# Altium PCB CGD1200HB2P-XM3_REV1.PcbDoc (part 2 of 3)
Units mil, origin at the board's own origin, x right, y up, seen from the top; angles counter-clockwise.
Board outline 2086.61 x 3149.61 mil, 6 copper layers (TOP, LAYER2, LAYER3, LAYER4, LAYER5, BOTTOM), stack 57.2 mil thick; 178 components, 101 nets, 513 pads, 419 vias.
Unrouted connection lines stored in the file: 206.
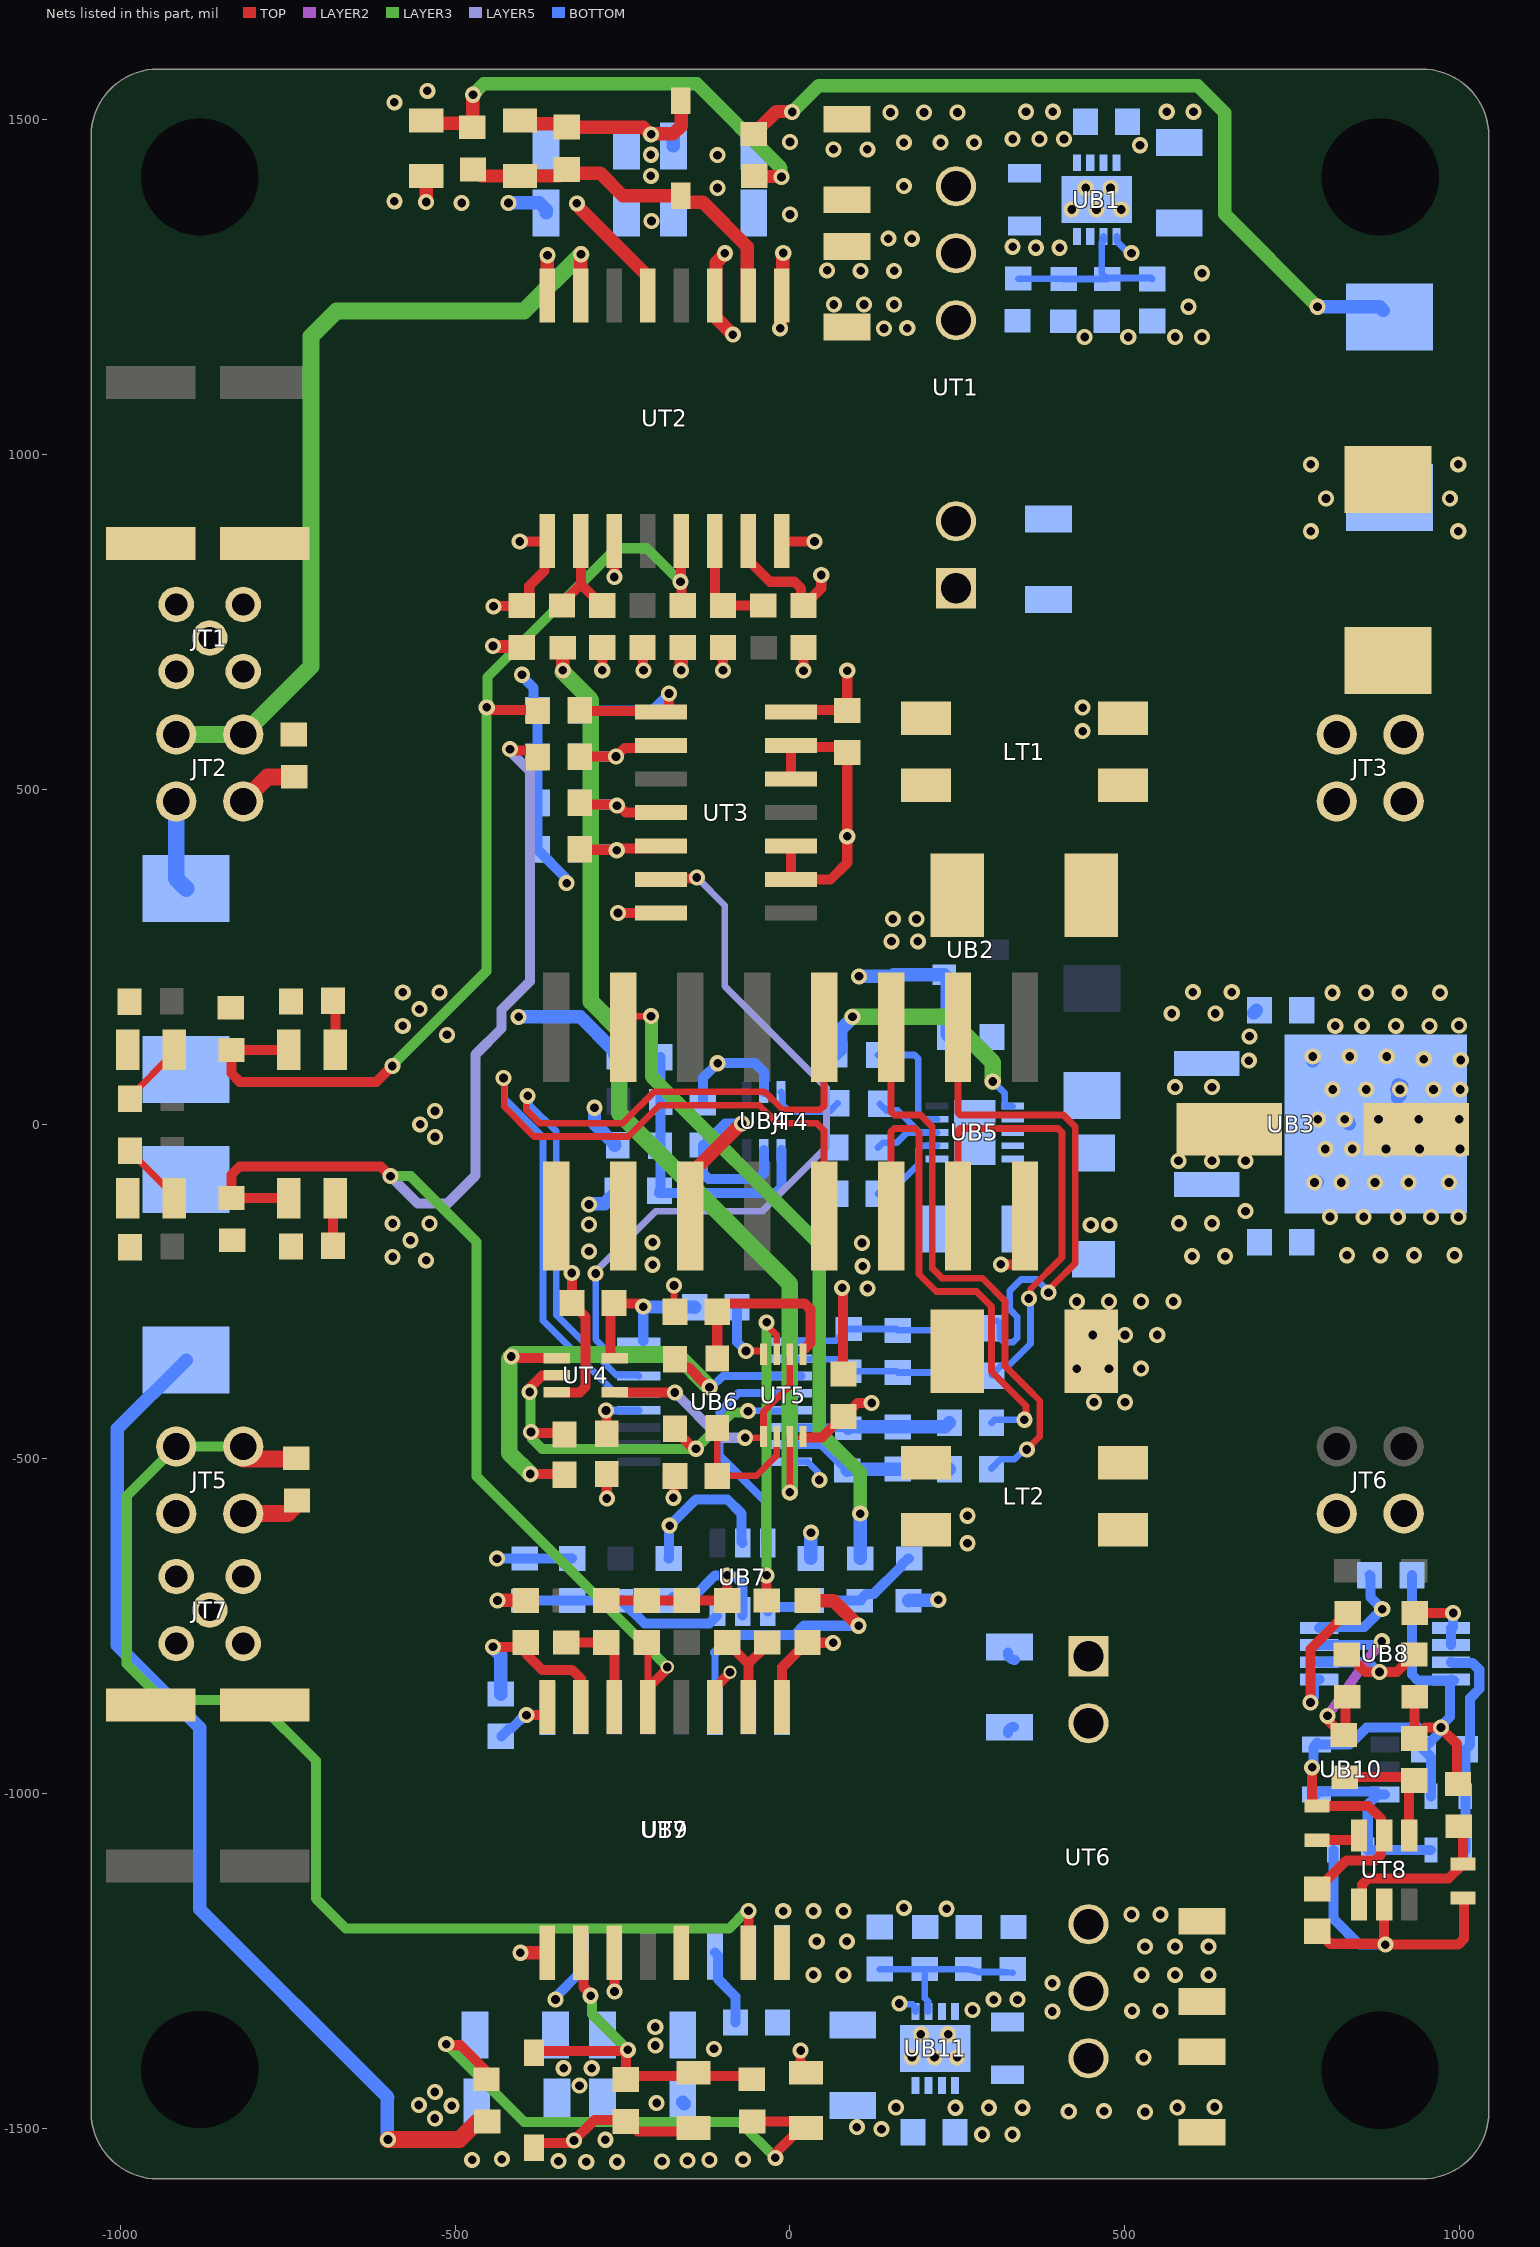
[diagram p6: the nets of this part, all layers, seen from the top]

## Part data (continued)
UB2: library part MOSFET_P_GSD, "MOSFET P-CH 30V 4.3A SOT23", Manufacturer="Diodes Incorporated", Package Size="TO-236-3, SC-59, SOT-23-3"
UB3: "IC REG LINEAR 5V 1A DPAK", Manufacturer="ON Semiconductor", Package Size="TO-252-3, DPak (2 Leads + Tab), SC-63"
UB4: library part BUFFER_2X_6P, "IC BUF NON-INVERT 5.5V SC70-6", Manufacturer="Texas Instruments", Package Size="6-TSSOP, SC-88, SOT-363", Supplier Part Number 1=595-SN74LVC2G17DCKR, Supply Voltage="1.65V ~ 5.5V"
UB5: library part MP5000A_5, "IC CURR LIMIT SWITCH", Manufacturer="Monolithic Power Systems Inc.", Package Size="10-VFDFN Exposed Pad", Supply Voltage="Not Required"
UB6: library part SN65C1167, "IC DIFF DVR/RCVR DUAL 16-TSSOP", Manufacturer="Texas Instruments", Manufacturer PN=SN65C1167EPWR, Package Size="16-TSSOP (0.173\", 4.40mm Width)", Supply Voltage="4.5V ~ 5.5V"
UB7: library part SN74LVC2G04, "IC INVERTER DUAL SHMT-T SOT-23-6", Manufacturer="Texas Instruments", Package Size=SOT-23-6, Supplier Part Number 1=74AH4903, Supply Voltage="1.65 V - 5.5 V"
UB8: "IC OPAMP GP 2 CIRCUIT 8MSOP", Case/Package=MSOP, Input Bias Current=1pA, Input Offset Voltage (Vos)=3mV, Input Offset Voltage-Max=5mV, Manufacturer=Microchip, Max Operating Temperature=125°C, Max Supply Voltage=5.5V, Min Operating Temperature=-40°C, Min Supply Voltage=2.4V, Nominal Supply Current=1mA, Output Current=25mA, Package Quantity=100, Power Supply Rejection Ratio (PSRR)=70dB, Supplier Part Number 1=MCP6292-E/MS-ND, Voltage Gain=110dB
UB9: "DGTL ISO 5.7KV GEN PURP 16SOIC", Manufacturer="Texas Instruments", Package Size="16-SOIC (0.295\", 7.50mm Width)", Supplier Part Number 1=595-ISO7810DWR, Supply Voltage="2.25V ~ 5.5V"
UB10: "IC VREF SHUNT ADJ 2% SOT23-5", Case/Package=SOT-23-5, Cathode Current=60uA, Manufacturer=STMicroelectronics, Max Input Voltage=10V, Max Operating Temperature=125°C, Max Output Current=30mA, Max Output Voltage=6V, Min Operating Temperature=-40°C, Min Output Voltage=1.24V, Package Quantity=1, Supplier Part Number 1=511-TS431IYLT, Temperature Coefficient=100ppm/°C, Tolerance=2%
UT1 UT6: library part MGJ2, "DC/DC CONVERTER 15V -5V 2W", Manufacturer="Murata Power Solutions Inc.", Package Size="0.77\" L x 0.39\" W x 0.50\" H (19.7mm x 10.0mm x 12.7mm)", Rated Power=2W, Supply Voltage="10.8 - 13.2 V"
UT2 UT7: "1500V ISOLATED HI UVLO 14.5V GAT", Manufacturer="Analog Devices", Manufacturer Part Number=ADUM4146CRWZ, Supplier Part Number 1=ADUM4146ARWZ
UT3: library part AND4_2X, "IC GATE AND 2CH 4-INP 14SOIC", Manufacturer="Texas Instruments", Manufacturer PN=SN74HC21DR, Package Size="14-SOIC (0.154\", 3.90mm Width)", Supplier Part Number 1=296-14842-1-ND, Supply Voltage="2 V - 6 V"
UT4: library part SN74LVC1G32, "IC GATE OR 1CH 2-INP SC-70-5", Manufacturer="Texas Instruments", Package Size="5-TSSOP, SC-70-5, SOT-353", Supply Voltage="1.65 V - 5.5 V"
UT5: library part XOR2_2X, "IC GATE XOR 2CH 2-INP US8", Manufacturer="ON Semiconductor", Manufacturer PN=NL27WZ86USG, Package Size="8-VFSOP (0.091\", 2.30mm Width)", Supply Voltage="1.65 V ~ 5.5 V"
UT8: library part LTC6992CS6-2, "IC OSC SILICON PROG TSOT23-6", Case/Package=SOT-23-6, Frequency=3.81Hz, Manufacturer="Analog Devices / Linear Technology", Max Operating Temperature=70°C, Max Supply Voltage=5.5V, Min Operating Temperature=0°C, Min Supply Voltage=2.25V, Operating Supply Current=365uA, Package Quantity=500, Supplier Part Number 1=584-C6992CS6-2TRMPBF

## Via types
v1: diameter 24.02, hole 12.99, TOP to BOTTOM, tented both sides, 415 vias
v2: diameter 20, hole 12.99, TOP to BOTTOM, tented both sides, 4 vias

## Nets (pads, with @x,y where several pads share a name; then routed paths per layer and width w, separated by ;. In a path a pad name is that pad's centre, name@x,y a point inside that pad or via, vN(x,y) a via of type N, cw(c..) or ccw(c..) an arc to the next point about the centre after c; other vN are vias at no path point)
0: CB9.2 CB10.2 CB11.2 CB12.2 CB13.1 CB14.1 CB15.2 CB16.2 CB17.2 CB18.2 CB19.2 CB20.1 CB21.2 CB24.2 CB25.2 CB26.2 CB29.1 CT4.2 CT5.2 CT6.2 CT7.2 CT8.2 CT9.2 CT10.2 CT11.2 CT12.2 CT13.2 CT14.2 CT15.2 CT16.2 CT17.2 CT18.2 CT19.2 CT20.2 CT21.2 DB4.C DT3.2 DT5.2 JT4.2 JT4.12 JT4.14 JT4.16 LT1.2 LT2.2 RB6.2 RB15.1 UB2.1 UB3.2 UB4.2 UB5.1 UB6.8 UB7.2 UB9.9 UB9.16 UT2.1 UT2.3 UT2.8 UT3.7 UT3.9 UT3.10 UT3.12 UT3.13 UT4.3 UT5.4 UT7.1 UT7.3 UT7.8 | length 4081.8
  TOP w10: v1(-173.14,-240.98) -173.14,-278.42 CT13.2@-172.1,-279.46 ; v1(-65.61,-338.99) -39.53,-338.99 UT5.4@-39.53,-343.73
  TOP w15: v1(-442.4,772.71) -441.73,773.37 -400.91,773.37 CT4.2@-400.24,774.04 -399.26,774.04 -389.19,784.11 -389.19,803.19 -366.12,826.26 -366.12,866.17 UT2.1@-362.01,870.28 ; v1(-403.31,869.48) UT2.1@-369.09,869.48 ; v1(-393.31,-882.45) -366.12,-882.45 -366.12,-874.71 UT7.8@-362.01,-870.59 ; UT4.3@-348.31,-400.65 -313.79,-400.65 -305.01,-391.86 -305.01,-288.22 -313.79,-279.44 -314.3,-279.44 -325.5,-268.24 CT12.2@-325.5,-267.25 -325.62,-267.13 -325.62,-222.64 v1(-325.74,-222.52) ; v1(-280.13,677.17) CT5.2@-280.13,711.05 ; CT16.2@-274.04,-711.16 CT17.2@-92.89,-711.16 ; v1(-262.09,816.54) v1(-262.09,816.54) UT2.3@-262.01,870.28 UT2.3@-262.01,870.28 ; v1(-256.78,314.94) UT3.7@-207.08,314.94 ; CT6.2@-220.08,711.05 -219.37,710.34 -219.37,677.88 v1(-218.66,677.17) v1@-218.66,675.94 ; v1(-174.12,-557.99) -172.81,-556.68 -172.81,-526.74 CT15.2@-171.5,-525.43 ; CT7.2@-162.38,692.35 -161.62,693.12 CT7.2@-161.62,709.46 ; UT7.3@-112.01,-870.59 -112.01,-841.85 -89.5,-819.34 v2(-89.5,-818.23) ; v1(-99.93,677.17) CT8.2@-99.95,711.03 ; CT17.2@-93.88,-711.16 CT17.2@-92.89,-711.16 ; v1(-93.74,-673.78) -93.81,-673.85 -93.81,-710.25 CT17.2@-92.89,-711.16 ; UT7.1@-12.01,-870.59 -12.19,-870.41 -12.19,-811.59 14.05,-785.36 15.03,-785.36 CT21.2@26.23,-774.16 26.44,-774.37 64.27,-774.37 v1(64.48,-774.58) ; UT2.8@-12.01,870.28 -11.21,869.48 v1(36.69,869.48) ; UT3.10@1.55,414.94 UT3.9@1.55,364.94 60.4,364.94 85.52,390.06 CT10.2@85.52,554.42 77.33,562.61 1.55,562.61 UT3.12@1.55,514.94 ; v1(20.15,676.67) CT9.2@20.14,711.05 ; v1@77.94,-249.52 78.97,-250.54 78.97,-372.46 CT14.2@79.99,-373.48 ; v1(314.85,-209.45) 338.76,-209.45 350.94,-197.27 JT4.2@350.94,-109.81
  TOP w20: v1(-436.42,-711.16) CT20.2@-394.15,-711.16 ; UT2.1@-362.01,870.28 UT2.1@-360.39,871.9 ; v1@-162.38,676.52 CT7.2@-162.38,692.35 ; CT7.2@-161.62,709.46 CT7.2@-160.02,711.05 ; JT4.12@-149.06,-137.37 -149.06,-75.36 -73.61,0.08 -72.44,0.08 v1(-71.67,0.85) ; v1@-99.93,675.05 v1(-99.93,677.17) ; CT11.2@935.04,3.19 v1(938.74,6.89)
  BOTTOM w10: UB6.8@0.42,-504.19 26.42,-504.19 41.26,-519.02 41.26,-528.84 v1(43.94,-531.52)
  BOTTOM w15: v1(-437.29,-648.78) -437.18,-648.67 -396.22,-648.67 RB15.1@-396.11,-648.56 CB24.2@-325.04,-648.56 ; CB29.1@-430.6,-913.95 -418.42,-901.77 -415.06,-901.77 -395.75,-882.45 -366.32,-882.45 -362.01,-878.14 UB9.9@-362.01,-871.18 ; v1(-400,670.68) -400,668.24 -382.58,650.81 -382.58,623.43 CB9.2@-376.56,617.41 ; CB9.2@-376.56,618.4 CB10.2@-376.56,548.36 -376.56,409.26 -335.04,367.74 -335.04,361.21 v1(-333.31,359.48) ; CB26.2@-180.93,-711.55 -175.35,-705.97 -143.97,-705.97 -112.16,-674.17 -94.13,-674.17 v1(-93.74,-673.78) -92.02,-675.51 -81.51,-675.51 -70.54,-686.47 UB7.2@-70.54,-733.44 ; CB21.2@-79.13,-273.8 -79.13,-325.47 v1(-65.61,-338.99) ; v1(-71.67,0.85) -96.61,0.87 -129.02,-31.54 CB15.2@-130,-31.54 -130,-73.46 -121.22,-82.25 -47.84,-82.25 -39.06,-73.46 UB4.2@-39.06,-38.82 ; UB9.16@-12.01,-871.18 -12.01,-811.41 24.83,-774.58 v1(64.48,-774.58)
  BOTTOM w20: v1(-405,159.95) -313.25,159.95 -263.76,110.47 -261.5,108.21 RB6.2@-261.5,103.98 ; v1(-300,-120.05) -299.24,-119.28 -276.76,-119.28 -257.87,-100.39 CB17.2@-257.87,-99.41 ; CB25.2@30.94,-648.56 31.23,-648.27 31.23,-610.25 v1(31.53,-609.96) ; v1(102.94,220.48) 152.49,220.48 154.95,222.94 UB2.1@230.49,222.94 234.5,218.94 234.5,133.94 CB14.1@238.5,129.94 ; UB3.2@780.4,94.04 v1(780.4,100.82) ; v1(782.95,-87.21) UB3.2@787.34,-87.21 ; v1(828.24,6.89) UB3.2@835.19,-0.06 ; v1(873.36,-87.21) UB3.2@874.49,-86.08 ; UB3.2@874.49,-0.06 UB3.2@896.71,-0.06 ; UB3.2@878.47,1.67 v1(878.47,6.89) ; UB3.2@905.43,51.48 910.54,56.59 UB3.2@913.13,56.59 ; UB3.2@907.13,38.9 UB3.2@907.13,54.89 ; UB3.2@908.19,51.48 UB3.2@908.19,58.94 ; UB3.2@910.54,42.3 v1(910.54,51.48) ; v1(938.74,6.89) UB3.2@955.83,6.89
  other v1: 265.11,-625.88 265.11,-584.74 115.99,-245.3 77.94,-244.52 108.5,-212.31 -205,-210.05 831.4,-195.87 881.62,-195.87 931.85,-195.87 992.13,-195.87 -300,-190.05 107.65,-177.62 -204.99,-176.64 -300,-150.05 449.01,-150.52 476.69,-150.52 806.24,-138.78 856.47,-138.78 907.48,-138.78 956.93,-138.78 998.03,-138.78 823.13,-87.21 923.59,-87.21 983.86,-87.21 799.21,-37.4 839.4,-37.4 889.62,-37.4 939.85,-37.4 1000.12,-37.4 -529.74,-19.52 -552.06,-0.52 788.06,6.89 999.02,6.89 -529.74,19.48 810.08,51.48 860.31,51.48 960.55,51.48 1000.6,51.48 1001.4,95.45 946.15,96.81 835.65,100.82 890.9,100.82 814.02,146.56 854.2,146.56 904.43,146.56 954.66,146.56 998.88,147.04 809.74,195.87 859.97,195.87 910.2,195.87 970.47,195.87 85.52,429.43 436.94,586.48 436.94,621.48 -162.38,677.17
5V: CB13.2 CB15.1 CB21.1 CB26.1 CB29.2 CT4.1 CT9.1 CT10.1 CT12.1 CT14.1 CT20.1 CT21.1 RB9.1 RB14.2 RT14.1 RT15.2 RT16.1 RT19.1 RT20.1 RT21.2 RT24.2 RT26.2 UB3.3 UB4.5 UB6.12 UB6.16 UB7.5 UB9.14 UT2.7 UT3.14 UT4.5 UT5.8 UT7.7 | length 2116.1
  TOP w15: v1(-443.31,-780.52) -400.51,-780.52 CT20.1@-394.15,-774.16 -394.15,-790.71 -370.01,-814.86 -325.2,-814.86 -312.01,-828.06 UT7.7@-312.01,-870.59 ; v1(-274.56,-427.67) -274.03,-428.19 -274.03,-462.03 RT24.2@-273.51,-462.56 ; RT26.2@-273.51,-522.56 -273.51,-558.8 v1(-273.27,-559.04) ; UT4.5@-261.7,-349.47 -267.47,-349.47 -267.84,-349.09 -267.84,-272.59 CT12.1@-262.51,-267.25 -261.91,-267.85 -226.16,-267.85 -221.41,-272.59 v1(-218.97,-272.59) ; UT2.7@-62.01,870.28 -62.01,841.54 -29.95,809.48 6.69,809.48 16.69,799.48 16.69,777.49 CT9.1@20.14,774.04 21.13,774.04 46.69,799.6 v1(46.69,819.48) ; UT3.14@1.55,614.94 4.54,617.93 CT10.1@85,617.93 ; UT5.8@19.52,-467.98 47.51,-467.98 79.01,-436.47 80.98,-436.47 100.94,-416.52 v1(121.94,-416.52) ; CT10.1@85.52,617.42 CT10.1@85,617.93 ; v1(85.52,676.67) 85.52,618.45 CT10.1@85,617.93
  TOP w20: v1(-443.27,713.55) -442.5,712.78 -401.97,712.78 CT4.1@-400.24,711.05 ; CT21.1@26.23,-711.16 26.62,-711.55 65.05,-711.55 v1(102.49,-748.99) ; v1(635,164.95) v1@635.76,164.19
  BOTTOM w10: UB9.14@-112.01,-871.18 -112.01,-789.21
  BOTTOM w12: v1@-274.75,-427.86 -274.42,-427.53 -226.35,-427.53 UB6.12@-226.21,-427.67
  BOTTOM w15: UB6.16@-218.97,-323.99 v1(-218.97,-272.59) ; CB26.1@-180.93,-648.56 -180.27,-647.9 -180.27,-600.21 -140.58,-560.52 -93.31,-560.52 -72.62,-581.21 -72.62,-623.29 UB7.5@-70.54,-625.36 ; CB15.1@-130,31.45 -130,68.53 -107.33,91.21 -52.56,91.21 -39.06,77.71 UB4.5@-39.06,47.96 ; -112.01,-789.21 -85.67,-762.88 6.83,-762.88 20.71,-748.99 v1(102.49,-748.99)
  BOTTOM w20: v1(-443.31,-780.52) -443.31,-781.6 -431.59,-793.33 CB29.2@-431.59,-850.96 ; v1(-291.8,24.3) -291.8,0.23 -261.5,-30.08 RB9.1@-261.5,-32.05 ; v1(-218.97,-272.59) -218.37,-273.2 -142.73,-273.2 CB21.1@-142.12,-273.8 ; RB14.2@177.02,-711.55 177.72,-710.85 220.64,-710.85 v1(221.34,-710.15) ; v1(635,164.95) v1@635.76,165.72 ; CB13.2@692.37,165.72 CB13.2@696.47,169.82
  other v1: -179.61,-599.55 -543.06,-203.52 -593.06,-198.52 -566.32,-173.52 -593.06,-148.52 -538.06,-148.52 575,54.95 630,54.95 -107.92,90.62 685.04,94.49 686.02,130.91 -512.06,133.09 -578.06,146.48 570,164.95 -553.06,171.48 -578.06,196.48 -523.06,196.48 601.38,196.85 659.45,196.85
12V: CB14.2 CB20.2 CT11.1 UB2.2 UB3.1 UB5.11
  other v1: 600.39,-197.37 649.6,-197.37 580.7,-148.15 629.92,-148.15 680,-130.05 580,-55.05 630,-55.05 680,-55.05 151.57,272.64 190.94,272.64 153.54,306.1 188.98,306.1
12V_SWITCHED: CB19.1 FT1.1 FT2.1 RB5.1 UB5.6 UB5.7 UB5.8 UB5.9 UB5.10 | length 485.1
  TOP w20: v1(428.19,-365.24) 428.19,-361.16 FT2.1@449.99,-339.36 ; v1(452.22,-315.12) 449.99,-317.34 FT2.1@449.99,-339.36 ; v1(476.24,-365.24) 450.37,-339.36 FT2.1@449.99,-339.36
  LAYER3 w25: v1(93.46,159.92) 235.02,159.92 302.7,92.24 v1(302.7,63.54)
  BOTTOM w10: v1(302.7,63.54) 320.78,45.46 320.78,26.8 320.9,26.68 UB5.6@332.41,26.68
  BOTTOM w20: RB5.1@68.5,104.04 76.21,111.75 76.21,141.59 93.46,158.83 v1(93.46,159.92)
  other v1: 453.74,-415.35 500.27,-415.35 524.3,-365.24 500.27,-315.12 548.32,-315.12 428.19,-265 476.24,-265 524.3,-265 572.35,-265
-5V_HS: CB1.2 CT3.2 RB1.1 UB1.1 UB1.2 UB1.3 UB1.9 UT1.5 | length 1.1
  TOP w20: v1(140.43,1187.58) v1@141.52,1187.58
  other v1: 175.08,1188 65.51,1223.43 110.51,1223.43 155.51,1223.43 420.53,1365.13 457.56,1365.13 494.58,1365.13 441.51,1397.12 478.53,1397.12 332.49,1470.23 372.49,1470.23 408.94,1470.23 352.49,1511.01 392.49,1511.01
-5V_LS: CB38.2 CT24.2 RB22.1 UB11.1 UB11.2 UB11.3 UB11.9 UT6.5
  other v1: 286.94,-1508.52 331.94,-1508.52 246.94,-1468.52 296.94,-1468.52 346.94,-1468.52 182.09,-1393.23 215.82,-1393.23 249.56,-1393.23 195.43,-1358.78 236.22,-1358.78 530,-1228 575,-1228 625,-1228 510,-1180.05 552.87,-1180.05
FAULT: UB6.15 UT3.6 | length 1136.9
  TOP w15: UT3.6@-191.99,365.41 -190.88,366.51 -140.57,366.51 v1(-139,368.08)
  TOP w20: UT3.6@-192.45,364.94 UT3.6@-191.99,365.41
  LAYER5 w10: v1(-290,-223.05) -290,-220.05 -200,-130.05 -41.09,-130.05 54.68,-34.28 54.68,54 -97.51,206.19 -97.51,326.59 v1(-139,368.08)
  BOTTOM w10: v1(-290,-223.05) -290,-321.43 -262.35,-349.09 -227.08,-349.09 UB6.15@-225.58,-350.59
FAULT-Output_N: JT4.8 UB6.13 | length 1248.3
  TOP w10: v1(-427.48,68.53) -426.35,67.4 -426.35,25.72 -381.92,-18.71 -241.33,-18.71 -194.66,27.96 -45.81,27.96 -19.11,1.26 39.73,1.26 50.78,-9.79 50.78,-109.65 JT4.8@50.94,-109.81
  BOTTOM w10: v1(-427.48,68.53) -426.35,67.4 -426.35,38.05 -368.74,-19.56 -368.74,-293.6 -267.66,-394.69 -262.06,-400.29 -227.08,-400.29 UB6.13@-225.58,-401.79
FAULT-Output_P: JT4.7 UB6.14 | length 1130.1
  TOP w10: v1(-391.49,41.96) -393.8,39.65 -393.8,21.46 -373.64,1.29 -249.61,1.29 -202.95,47.96 -37.53,47.96 -10.83,21.26 44.92,21.26 50.78,27.12 50.78,143.97 JT4.7@50.94,144.13
  BOTTOM w10: v1(-391.49,41.96) -388.81,39.28 -388.81,28.79 -348.74,-11.27 -348.74,-285.32 -259.38,-374.69 -227.08,-374.69 UB6.14@-225.58,-376.19
FLT_HS: CT7.1 DT4.2 RT9.1 RT16.2 UT2.5 | length 1578.7
  TOP w15: DT4.2@-748.5,110.78 -748.76,110.52 RT16.2@-833.64,110.52 -833.64,75.31 -821.33,63 -617.25,63 v1(-593.56,86.7) ; v1(-452.68,621.9) -450.24,621.9 -446.3,617.96 -378.08,617.96 RT9.1@-376.56,616.43 ; v1(-163.31,809.48) -161.67,807.84 -161.67,775.69 CT7.1@-160.02,774.04 ; v1@-162.01,810.79 -162.66,811.44 -162.66,869.63 UT2.5@-162.01,870.28
  LAYER3 w15: v1(-593.56,86.7) -593.56,87.67 -453.31,227.91 -453.31,621.26 -451.52,623.06 -451.52,667.39 -259.42,859.48 -213.31,859.48 v1(-163.31,809.48)
FLT_LS: CT18.1 DT6.2 RT11.1 RT19.2 UT7.5 | length 2408.7
  TOP w10: UT7.5@-212.01,-899.33 CT18.1@-212.01,-774.16
  TOP w15: DT6.2@-748.5,-110.9 -748.76,-110.64 RT19.2@-833.64,-110.64 -833.64,-75.42 -821.62,-63.4 -610.73,-63.4 v1(-596.25,-77.88) ; v1@-420.8,559.48 v1@-419.08,557.76 ; v1(-417.81,559.48) -416.08,557.76 -386.77,557.76 -376.56,547.54 RT11.1@-376.56,547.38 ; UT7.5@-212.01,-899.33 -212.01,-841.85 -185.04,-814.88 -185.04,-812.24 v2(-183.31,-810.52)
  LAYER3 w15: v1(-596.25,-77.88) -565.96,-77.88 -537.61,-106.23 -468.01,-175.84 -468.01,-525.82 v2(-183.31,-810.52)
  LAYER5 w15: v1(-596.25,-77.88) -555.15,-118.97 -511.4,-118.97 -469.62,-77.19 -469.62,103.48 -430.51,142.58 -430.51,170.52 -388.01,213.02 -388.01,526.69 -417.81,556.49 v1(-417.81,559.48)
"Gate Sense HS": JT1.1 JT2.1 JT2.3 RT5.2 RT6.2 RT10.1 UT2.15 | length 1251.3
  TOP w20: UT2.15@-312.01,1236.82 v1(-312.01,1298.32)
  LAYER3 w25: JT2.1@-916.15,581.45 JT2.3@-816.15,581.45 -715.01,682.59 -715.01,1175.53 -677.06,1213.48 -396.84,1213.48 v1(-312.01,1298.32)
"Gate Sense LS": JT5.1 JT5.3 JT7.1 RT25.1 RT33.2 RT34.2 UT7.15 | length 1853.2
  TOP w15: UT7.15@-61.91,-1237.03 -61.96,-1236.98 -61.96,-1174.59 v1(-61.91,-1174.54)
  TOP w20: UT7.15@-62.01,-1237.13 UT7.15@-61.91,-1237.03
  TOP w25: JT5.3@-827.51,-488.99 -816.44,-500.06 RT25.1@-732.13,-500.06
  LAYER2 w10: JT5.3@-832.08,-493.54 JT5.3@-832.08,-481.54
  LAYER3 w15: JT5.3@-816.15,-481.54 JT5.1@-916.15,-481.54 -990,-555.4 -990,-806.02 -935.98,-860.05 -797.75,-860.05 -707.48,-950.31 -707.48,-1156.35 -662.69,-1201.14 -90.95,-1201.14 -64.35,-1174.54 v1(-61.91,-1174.54)
HS-DRAIN: DT2.C JT3.1 JT3.2 JT3.3 JT3.4
HS-PWM: RT8.1 UT5.7 | length 1485.1
  TOP w10: v1(-0.16,-549.9) UT5.7@-0.16,-466.23
  TOP w20: RT8.1@-339.21,711.05 -339.14,710.99 -339.14,677.23 v1(-339.08,677.17) v1@-339.08,674.43
  LAYER3 w25: v1@-339.08,674.43 -297.31,632.66 -297.31,182.63 -255.01,140.33 -255.01,16.1 -0.16,-238.74 v1(-0.16,-549.9)
HS-PWM-INPUT: RT22.1 RT26.1 UB6.3 UT4.1 | length 838.2
  TOP w15: v1(-415.94,-347.2) -413.5,-347.2 -411.23,-349.47 UT4.1@-348.31,-349.47 ; v1(-387.51,-522.56) -336.5,-522.56 RT26.1@-336.5,-523.54 ; RT22.1@-171.5,-351.04 -171.5,-353.01 -161.29,-363.23 -151.13,-363.23 -139.73,-374.63 -139.73,-375.33 -122.04,-393.02 v1(-120.05,-393.02)
  LAYER3 w25: v1(-415.94,-347.2) -419.06,-350.32 -419.06,-491.01 v1(-387.51,-522.56) ; v1@-412.82,-344.09 -168.99,-344.09 v1(-120.05,-393.02)
  BOTTOM w12: v1(-120.05,-393.02) -116.81,-393.02 -99.98,-376.19 UB6.3@17.47,-376.19
HS-PWM_N: JT4.4 LB2.1 | length 672.7
  TOP w10: JT4.4@250.94,-109.81 250.94,-11.31 cw(c255.63,-11.31) 255.63,-6.62 400.15,-6.62 406,-12.48 406,-199.24 359.37,-245.87 359.37,-257.84 v1(356.69,-260.52)
  BOTTOM w10: LB2.1@301.49,-374.56 315.19,-360.86 326.37,-360.86 359.2,-328.04 359.2,-266.99 356.69,-264.48 v1(356.69,-260.52)
HS-PWM_P: JT4.3 LB1.1 | length 755.3
  TOP w10: JT4.3@250.94,116.57 250.94,18.07 ccw(c255.63,18.07) 255.63,13.38 408.43,13.38 426,-4.19 426,-207.52 393.08,-240.44 393.08,-240.9 386.08,-247.91 v1(386.08,-251.71)
  BOTTOM w10: LB1.1@309.64,-293.93 313.34,-297.63 313.34,-319.75 319.2,-325.61 333.34,-325.61 339.2,-319.75 339.2,-287.81 328.22,-276.82 328.22,-248.72 344.89,-232.04 368.48,-232.04 386.08,-249.64 v1(386.08,-251.71)
HS-SOURCE: CB1.1 CB2.1 CB3.2 CB4.2 CB5.1 CB6.2 CT1.2 CT2.2 CT3.1 DB2.C DT1.A JT1.2 JT1.3 JT1.4 JT1.5 JT2.2 JT2.4 RB2.2 RT2.2 RT10.2 UB1.4 UB1.5 UT1.6 UT2.11 | length 708.7
  TOP w20: RT2.2@-403.06,1497.82 -398.13,1492.9 -337.98,1492.9 CT2.2@-332.92,1487.84 ; CT2.2@-333.06,1487.98 CT2.2@-332.92,1487.84 ; DT1.A@-163.06,1527.35 -162.43,1526.72 -162.43,1489.85 -174.14,1478.13 -206.47,1478.13 v1(-207.24,1477.36) -208.32,1477.36 -218.8,1487.84 CT2.2@-332.92,1487.84 ; v1(-97.23,1299.79) -97.23,1298.71 -110.39,1285.54 -110.39,1203.38 v1(-85.29,1178.28)
  TOP w25: JT2.4@-816.15,481.45 -779.79,517.81 -740.65,517.81 RT10.2@-740,518.46
  BOTTOM w10: UB1.5@487.61,1324.82 487.61,1318.32 503.3,1302.64 507.31,1302.64 v1(510,1299.95)
  BOTTOM w20: CB2.1@-174.01,1459.94 CB2.1@-174.01,1474.94
  BOTTOM w25: JT2.2@-916.15,481.45 -916.15,366.32 DB2.C@-901.31,351.48
  other v1: 105.51,1273.62 155.51,1273.62 55.48,1274.37 146.93,1321.61 181.94,1321.48 -206.7,1347.91 -207.68,1415.35 -207.68,1446.85 522.49,1461.01 562.49,1511.01 602.49,1511.01
HS-VDD: CB3.1 CB6.1 CT1.1 RT1.1 UT1.7 UT2.13 | length 285.2
  TOP w20: v1(-543.06,1376.48) RT1.1@-543.06,1415.14 ; v1(-318.13,1374.27) -317.36,1373.51 -317.36,1370.91 -213.62,1267.17 -213.62,1238.43 UT2.13@-212.01,1236.82
  BOTTOM w20: v1(-420,1374.95) -374.01,1374.95 -364.01,1364.95 CB6.1@-364.01,1359.94
  other v1: -490,1374.95 -590.56,1377.44 170,1399.95 65,1454.95 115.51,1454.95 170,1464.95 225,1464.95 275,1464.95 150,1509.95 200,1509.95 250,1509.95 -590.56,1525.07 -541.34,1542.32
HS-VSS: CB2.2 CB4.1 CB5.2 CB7.1 RB1.2 RB3.1 RB4.1 UB1.7 UB1.8 UT2.9 UT2.16 | length 174.6
  TOP w20: UT2.16@-362.01,1236.82 v1(-362.01,1296.86) ; v1(-14.59,1187.72) -14.59,1188.81 -13.62,1189.78 -13.62,1235.2 -10.73,1238.09 -10.73,1299.55 v1(-9.96,1300.32)
  other v1: 440,1174.95 505,1174.95 575,1174.95 615,1174.95 595,1219.95 615,1269.95 367.13,1308.07 402.56,1308.07 332.49,1309.48 0,1357.75 -108.27,1397.12 -108.27,1446.33 0,1466.02
LOGIC-ENABLE: JT4.13 RB13.2 | length 1013.6
  TOP w10: JT4.13@-249.06,116.57 -249.06,141.5 -229.55,161.01 v1(-207.51,161.01)
  LAYER3 w20: v1(-207.51,161.01) -206.74,160.24 -206.74,70.93 43.94,-179.76 43.94,-459.01 104.99,-520.06 v1(104.99,-581.7)
  BOTTOM w20: RB13.2@104.99,-648.56 v1(104.99,-581.7)
LS-PWM: RT30.1 UT5.3 | length 474.2
  TOP w10: v1(-34.83,-296.06) -34.83,-299.85 -19.85,-314.83 UT5.3@-19.85,-348.98
  TOP w15: RT30.1@-34.81,-711.16 v1@-34.81,-671.73
  LAYER3 w15: v1@-34.82,-671.72 v1@-34.82,-296.07
  other v1: -34.81,-673.78
LS-PWM-INPUT: RT23.1 RT24.1 UB6.5 UT4.2 | length 633.9
  TOP w15: v1(-388.55,-400.05) -386.82,-398.32 -386.82,-392.51 -369.75,-375.43 -348.69,-375.43 UT4.2@-348.31,-375.06 ; v1(-386.64,-459.86) -384.92,-461.58 -339.54,-461.58 RT24.1@-337.82,-459.86 ; RT23.1@-171.5,-456.7 -145.1,-483.1 -141.89,-483.1 v1(-140.17,-484.83)
  LAYER3 w15: v1(-388.55,-400.05) -387.6,-401 -387.6,-458.9 -384.92,-461.58 -384.92,-469.86 -369.95,-484.83 v1(-140.17,-484.83) -85.7,-430.36 -64.25,-430.36 v1(-62.52,-428.63)
  BOTTOM w10: v1(-62.52,-428.63) -61.9,-428.01 -0.2,-428.01 UB6.5@0.42,-427.39
LS-PWM_N: JT4.6 LB3.1 | length 727.1
  TOP w10: JT4.6@150.94,-109.81 150.94,-11.31 155.63,-6.62 186.75,-6.62 192.61,-12.48 192.61,-224.26 218.42,-250.06 278.75,-250.06 300.99,-272.3 300.99,-369.4 346.57,-414.98 352.43,-420.83 352.43,-439.03 v1(349.94,-441.52)
  BOTTOM w10: LB3.1@300.87,-446.08 305.43,-441.52 v1(349.94,-441.52)
LS-PWM_P: JT4.5 LB4.1 | length 825.3
  TOP w10: JT4.5@150.94,116.57 150.94,18.07 155.63,13.38 195.04,13.38 212.61,-4.19 212.61,-215.97 226.7,-230.06 287.04,-230.06 320.99,-264.02 320.99,-361.11 354.86,-394.98 372.95,-413.07 372.95,-466.52 v1(353.65,-485.83)
  BOTTOM w10: LB4.1@300.87,-514.15 314.57,-500.45 335.23,-500.45 349.85,-485.83 v1(353.65,-485.83)
LS-RTD-REF: CB30.2 RB16.1 RB17.2 UB8.3 | length 324.2
  BOTTOM w15: UB8.3@986.94,-803.52 988.3,-804.88 1019.21,-804.88 1028.99,-814.66 1028.99,-843.56 1015.49,-857.06 1015.49,-926.47 1008.28,-933.67 1008.28,-1003.36 RB16.1@1008.13,-1003.52 RB17.2@1008.13,-1083.52
LS-SOURCE: CB27.1 CB32.2 CB33.2 CB34.1 CB35.2 CB36.1 CB37.2 CB38.1 CT23.1 CT24.1 CT25.2 CT26.2 DT7.A JT5.2 JT5.4 JT7.2 JT7.3 JT7.4 JT7.5 RB18.1 RB19.2 RT25.2 RT38.1 RT39.2 UB8.8 UB9.3 UB11.4 UB11.5 UT6.6 UT7.11 UT8.5 | length 1281
  TOP w15: DT7.A@-382.06,-1528.4 -375.05,-1521.39 -328.91,-1521.39 -324.78,-1517.25 v1(-322.34,-1517.25) ; v1@-324.06,-1518.98 -292.1,-1487.01 -244.07,-1487.01 -227.23,-1503.86 -149.05,-1503.86 RT39.2@-144.06,-1498.86 ; v1(-262.01,-1295.1) UT7.11@-262.01,-1237.13 ; CT23.1@786.94,-1205.01 787.93,-1205.01 806.63,-1223.71 887.44,-1223.71 v1(888.78,-1225.05) 997.43,-1225.05 1006.22,-1216.26 1006.22,-1157.98 1005,-1156.75 RT38.1@1005,-1155.64 ; v1@886.94,-1225.05 UT8.5@886.94,-1165.09
  TOP w25: JT5.4@-816.15,-581.54 -749.65,-581.55 -741.59,-573.49 -731.15,-563.05 RT25.2@-732.31,-563.05
  BOTTOM w10: v1(163.32,-1312.94) 164.31,-1313.94 182.87,-1313.94 187.37,-1318.44 UB11.5@187.37,-1324.94
  BOTTOM w15: UB9.3@-112.01,-1236.93 -107.7,-1241.24 -107.7,-1276.13 -81.5,-1302.33 CB32.2@-81.5,-1341.33 ; UB8.8@790.09,-752.34 791.45,-750.98 857.34,-750.98 881.27,-727.05 v1(884.13,-724.18) 866.87,-706.92 866.87,-674.93 CB27.1@865.45,-673.52 ; RB18.1@811.35,-1083.52 811.35,-1186.4 850,-1225.05 v1(888.78,-1225.05)
  other v1: -304.13,-1549.21 -257.87,-1549.21 -345.47,-1548.23 -275.59,-1516.27 136.69,-1500.52 99.79,-1497.42 158.28,-1468.03 -314.06,-1435.58 -337.79,-1409.6 -295.82,-1409.6 391.73,-1324.8 510.83,-1323.82 553.15,-1323.82 391.73,-1282.48 525,-1270.05 575,-1270.05 625,-1270.05
LS-VDD: CB33.1 CB37.1 CT25.1 RT40.1 UT6.7 UT7.13 | length 39.3
  TOP w15: UT7.13@-162.92,-1238.04 UT7.13@-162.76,-1238.2 ; v1(16,-1383.05) 16,-1410.24 RT40.1@21.94,-1416.19
  BOTTOM w20: CB37.1@-160.01,-1460.06 CB37.1@-157.55,-1462.52
  other v1: -191.06,-1548.52 -153.06,-1547.52 -120.06,-1546.52 -70,-1546.05 416.14,-1474.13 529.94,-1474.98 468.68,-1473.67 578.35,-1468.21 633.94,-1467.44 -199.06,-1461.52 527.94,-1393.62 -113.31,-1380.52 -200.92,-1375.6 -201.15,-1347.84
LS-Vref: RB17.1 RB18.2 UB10.3 UB10.4 | length 286.9
  BOTTOM w15: UB10.4@785.76,-1000.92 790.07,-996.61 UB10.3@875.17,-996.61 ; UB10.3@888.13,-1000.92 875.17,-1000.92 875.17,-1004.03 873.97,-1005.23 873.47,-1005.23 862.54,-1016.16 RB18.2@862.54,-1083.52 862.84,-1083.82 956.64,-1083.82 RB17.1@956.94,-1083.52
LS-VSS: CB27.2 CB30.1 CB31.1 CB32.1 CB34.2 CB35.1 CB36.2 CT22.2 CT23.2 JT6.2 JT6.4 RB16.2 RB20.1 RB21.1 RB22.2 RT31.1 RT36.2 RT37.1 UB8.4 UB9.1 UB9.7 UB10.5 UB11.7 UB11.8 UT7.9 UT7.16 UT8.2 | length 1349.7
  TOP w15: v1(779.53,-960.34) 779.53,-1016.45 781.01,-1017.93 863.45,-1017.93 882.24,-1036.71 882.24,-1057.24 UT8.2@886.94,-1061.94 882.24,-1066.65 882.24,-1090.67 873.45,-1099.46 830.49,-1099.46 787.93,-1142.02 CT23.2@786.94,-1142.02 ; RT31.1@932.93,-855.01 932.44,-855.51 932.44,-916.53 932.93,-917.02 948.99,-900.96 v1(972,-900.96) 972,-901.85 995.96,-925.81 RT37.1@995.96,-985.06
  TOP w20: v1(-402.4,-1237.13) UT7.9@-362.01,-1237.13 ; UT7.16@-12.01,-1237.13 -12.01,-1265.87 UT7.16@-10.39,-1267.48
  BOTTOM w15: v1(-350,-1307.05) -348.28,-1305.32 -348.28,-1301.55 -316.32,-1269.59 UB9.7@-312.01,-1236.54 ; v1(779.53,-960.34) 781.26,-958.61 781.26,-930.43 785.57,-926.12 UB10.5@785.76,-926.12 785.76,-924.7 786.94,-923.52 789.54,-926.12 835.57,-926.12 860.88,-900.8 938.16,-900.8 938.16,-926.23 CB30.1@945.45,-933.52 ; CB27.2@928.44,-673.52 928.44,-821.76 937.23,-830.54 958.71,-830.54 958.79,-830.47 UB8.4@991.3,-830.47 ; RB16.2@956.94,-1003.52 956.94,-963.52 956.65,-963.22 956.65,-944.72 CB30.1@945.45,-933.52 ; UB8.4@986.94,-829.11 986.73,-829.11 985.37,-830.47 985.37,-885.16 972,-898.52 v1(972,-900.96) 970.28,-902.69 970.28,-907.71 945.45,-932.53 CB30.1@945.45,-933.52
  other v1: -474.41,-1546.26 -430.12,-1545.28 -530.03,-1484.59 -505.06,-1465.52 -554.06,-1464.52 -530.03,-1445.06 272.64,-1322.52 304.13,-1307.09 339.57,-1307.09 35,-1270.05 80,-1270.05 40,-1220.05 85,-1220.05 -10,-1175.05 35,-1175.05 80,-1175.05 233.94,-1171.52 170,-1170.05
NetCB7_2: CB7.2 RB2.1 RB3.2 RB4.2 UB1.6 | length 267.5
  BOTTOM w10: RB2.1@340.67,1261.98 408.29,1261.98 RB4.2@408.83,1261.44 470,1261.44 RB3.2@473.83,1261.44 465.46,1269.81 465.46,1315.84 467.93,1318.32 UB1.6@467.93,1324.82 ; RB3.2@475.21,1262.82 539.47,1262.82 CB7.2@540.86,1261.44
NetCB8_1: CB8.1 LT1.4 UT1.1
NetCB8_2: CB8.2 LT1.3 UT1.2
NetCB9_1: CB9.1 RT9.2 UT3.1 | length 303.1
  TOP w15: RT9.2@-313.56,617.42 -312.33,616.18 -207.69,616.18 -206.45,614.94 -183.96,614.94 -180.46,618.44 v1(-180.46,642.49)
  BOTTOM w15: CB9.1@-313.57,617.41 -205.53,617.41 v1(-180.46,642.49)
NetCB10_1: CB10.1 RT11.2 UT3.2 | length 167.9
  TOP w15: RT11.2@-313.56,548.36 -313.24,548.69 v1(-259.82,548.69) -247.07,561.44 -209.95,561.44 UT3.2@-206.45,564.94
  BOTTOM w15: CB10.1@-313.57,548.36 -313.4,548.52 -259.99,548.52 v1(-259.82,548.69)
NetCB11_1: CB11.1 RT12.2 UT3.4 | length 170.1
  TOP w15: RT12.2@-313.56,479.3 -311.13,476.87 -259.96,476.87 v1(-258.24,475.14) -255.8,475.14 -245.59,464.94 UT3.4@-206.45,464.94
  BOTTOM w15: CB11.1@-313.57,479.3 -311.13,476.87 -259.96,476.87 v1(-258.24,475.14)
NetCB12_1: CB12.1 RT13.2 UT3.5 | length 166.2
  TOP w15: RT13.2@-313.56,410.25 -312.74,409.42 -259.36,409.42 v1(-258.53,408.59) -256.09,408.59 -253.24,411.44 -209.95,411.44 UT3.5@-206.45,414.94
  BOTTOM w15: CB12.1@-313.57,410.25 -312.74,409.42 -259.36,409.42 v1(-258.53,408.59)
NetCB16_1: CB16.1 RB8.1 UB5.3 | length 174.5
  BOTTOM w10: CB16.1@131.49,-35.06 138.47,-28.08 159.33,-28.08 174.73,-12.69 193.62,-12.69 ; RB8.1@133.99,30.02 143.93,20.09 160.85,20.09 193.62,-12.69 ; UB5.3@219.42,-12.69 193.62,-12.69
NetCB17_1: CB17.1 RB6.1 RB7.1 RB9.2 UB4.1 | length 442.8
  BOTTOM w15: CB17.1@-195.78,-103.25 -21.57,-103.25 -12.78,-94.46 UB4.1@-12.78,-38.82 ; CB17.1@-194.88,-99.41 -193.21,-97.74 -193.21,-33.16 RB9.2@-193.9,-32.48 -193.48,-32.06 -193.48,32.41 RB7.1@-193.06,32.83 RB6.1@-193.06,99.8
NetCB18_1: CB18.1 UB5.2 | length 130.5
  BOTTOM w10: CB18.1@131.49,-104.11 143.14,-92.46 159.33,-92.46 191.49,-60.3 191.49,-38.35 197.35,-32.49 219.3,-32.49 UB5.2@219.42,-32.37
NetCB22_1: CB22.1 LB2.2 RB10.2 UB6.2 | length 248.2
  BOTTOM w10: UB6.2@0.42,-351.06 68.84,-351.06 RB10.2@86.78,-368.99 158.86,-368.99 CB22.1@160.83,-370.96 231.82,-370.96 LB2.2@237.88,-377.02
NetCB22_2: CB22.2 LB1.2 RB10.1 UB6.1 | length 246.1
  BOTTOM w10: UB6.1@0.42,-324.99 1.69,-323.72 68.08,-323.72 85.79,-306 158.86,-306 160.83,-307.97 LB1.2@237.88,-307.97
NetCB23_1: CB23.1 LB3.2 RB11.2 UB6.6 | length 241.1
  BOTTOM w12: UB6.6@0.42,-453.46 86.13,-453.46 RB11.2@86.78,-454.11
  BOTTOM w20: RB11.2@86.78,-454.11 88.75,-452.14 CB23.1@160.83,-452.14 231.82,-452.14 LB3.2@237.88,-446.08
NetCB23_2: CB23.2 LB4.2 RB11.1 UB6.7 | length 254.5
  BOTTOM w12: UB6.7@-0.02,-479.06 46.76,-479.06 84.81,-517.1 RB11.1@85.79,-517.1
  BOTTOM w20: RB11.1@85.79,-517.1 87.76,-515.13 CB23.2@160.83,-515.13 LB4.2@237.88,-515.13
NetCB24_1: CB24.1 RB12.1 RB15.2 UB7.3 | length 306.8
  BOTTOM w15: RB15.2@-397.1,-711.55 CB24.1@-325.04,-711.55 RB12.1@-253.97,-711.55 -251.02,-711.55 -216.82,-745.76 -120.36,-745.76 UB7.3@-109.12,-734.52
NetCB25_1: CB25.1 RB13.1 RB14.1 UB7.1 | length 250.7
  BOTTOM w15: UB7.1@-32.91,-727.96 -32.91,-724.81 -28.83,-720.73 21.76,-720.73 CB25.1@30.94,-711.55 105.98,-711.55 RB13.1@104.01,-711.55 114.23,-701.34 125.23,-701.34 165.82,-660.75 165.82,-658.78 176.04,-648.56 RB14.1@178.01,-648.56
NetCB28_1: CB28.1 LT2.4 UT6.1 | length 16.8
  BOTTOM w15: CB28.1@325.24,-789.25 ccw(c335.92,-789.25) CB28.1@335.92,-799.93
NetCB28_2: CB28.2 LT2.3 UT6.2 | length 14.6
  BOTTOM w15: CB28.2@325.24,-909.25 cw(c334.57,-909.25) CB28.2@334.57,-899.93
NetCB31_2: CB31.2 RB19.1 RB20.2 RB21.2 UB11.6 | length 264.6
  BOTTOM w10: CB31.2@134.13,-1261.55 RB21.2@201.16,-1261.55 ; UB11.6@206.05,-1324.94 206.05,-1309.56 201.16,-1304.67 RB21.2@201.16,-1261.55 ; RB19.1@332.7,-1267.01 318.02,-1265.81 280.84,-1265.81 RB20.2@266.16,-1261.55 RB21.2@201.16,-1261.55
NetCT2_1: CT2.1 DT1.C RT2.1 RT3.2 UT2.10 | length 529.2
  TOP w20: RT3.2@-473.06,1424.99 -471.09,1424.99 -461.24,1415.14 -343.88,1415.14 -334.04,1424.99 CT2.1@-333.06,1424.99 ; CT2.1@-332.07,1424.99 -326.63,1419.54 -283.37,1419.54 -249.44,1385.61 DT1.C@-163.06,1385.61 ; DT1.C@-158.29,1375.93 -129.76,1375.93 -63.62,1309.79 -63.62,1238.43 UT2.10@-62.01,1236.82
NetCT5_1: CT5.1 RT8.2 UT2.2 | length 152.7
  TOP w15: RT8.2@-340.19,774.04 -340.19,777.12 -312.01,805.3 ; UT2.2@-312.01,870.28 -312.01,805.3 ; CT5.1@-280.13,774.04 -311.4,805.3 -312.01,805.3
NetCT8_1: CT8.1 RT7.2 UT2.6 | length 161.3
  TOP w15: UT2.6@-112.01,870.28 -112.01,786.08 CT8.1@-99.97,774.04 RT7.2@-39.91,774.04
NetCT13_1: CT13.1 RT22.2 UT5.1 | length 280.7
  TOP w15: RT22.2@-108.51,-350.06 CT13.1@-108.51,-280.06 -108.51,-279.07 -97.31,-267.87 -88.68,-267.87 -88.52,-267.72 21.63,-267.72 30.42,-276.5 30.42,-327.08 UT5.1@22.02,-335.48
NetCT15_1: CT15.1 RT23.2 UT5.6 | length 206.9
  TOP w10: RT23.2@-108.51,-453.74 CT15.1@-108.51,-525.43 -108.14,-525.06 -50.01,-525.06 -19.85,-494.9 UT5.6@-19.85,-460.98
NetCT16_1: CT16.1 RT29.2 UT7.6 | length 161.5
  TOP w15: RT29.2@-334.1,-774.16 CT16.1@-274.04,-774.16 -262.01,-786.19 UT7.6@-262.01,-870.59
NetCT17_1: CT17.1 RT30.2 UT7.2 | length 152.9
  TOP w15: CT17.1@-93.88,-774.16 -62.62,-805.42 -62.01,-805.42 ; UT7.2@-62.01,-870.59 -62.01,-805.42 ; RT30.2@-33.82,-774.16 -33.82,-777.24 -62.01,-805.42
NetCT22_1: CT22.1 RT35.1 UT8.1 | length 191.2
  TOP w15: RT35.1@827.93,-975.01 926.94,-975.01 CT22.1@931.94,-980.01 924.35,-987.61 UT8.1@924.35,-1061.94
NetCT26_1: CT26.1 DT7.C RT39.1 RT42.2 UT7.10 | length 550
  TOP w15: DT7.C@-382.06,-1386.66 -379.49,-1384.09 -246.44,-1384.09 -244.44,-1382.08 v1(-242,-1382.08) ; UT7.10@-312.01,-1237.13 -307.89,-1241.24 -307.89,-1288.5 -297.49,-1298.89 v1(-297.49,-1301.27) ; v1@-244.94,-1385.03 -243.72,-1386.25 -245.03,-1387.55 CT26.1@-245.06,-1426.03 -240.13,-1421.11 -144.06,-1421.11 -61.98,-1421.11 RT42.2@-57.06,-1426.03
  LAYER3 w15: v1(-297.49,-1301.27) -295.77,-1302.99 -295.77,-1328.31 v1(-242,-1382.08)
NetDB1_A: DB1.A RT4.1 | length 1197.8
  TOP w20: RT4.1@-54.04,1477.98 -20.6,1511.42 2.49,1511.42 v1(3.26,1510.65)
  LAYER3 w20: v1(3.26,1510.65) 42.55,1549.94 608.48,1549.94 648.94,1509.48 648.94,1358.41 v1(787.4,1219.96)
  BOTTOM w20: v1(787.4,1219.96) 880.23,1219.96 DB1.A@885.82,1214.36
NetDB1_C: DB1.C DT2.A
  other v1: 777.57,884.79 997.57,884.79 800.07,933.73 985.07,933.73 777.57,984.79 997.57,984.79
NetDB2_A: DB2.A DB5.C
NetDB3_A: DB3.A DB4.A
NetDB5_A: DB5.A RT41.1 | length 1532.3
  TOP w25: v1(-600.01,-1515.93) -492.98,-1515.93 -466.08,-1489.02 RT41.1@-452.07,-1489.02
  BOTTOM w20: DB5.A@-901.31,-352.52 -1003.94,-455.15 -1003.94,-778.31 -881.06,-901.2 -881.06,-1172.09 -600.01,-1453.14 ; v1@-600.99,-1515.93 -600.99,-1453.14
NetDT3_1: DT3.1 RT17.1 | length 100.6
  TOP w10: RT17.1@-985.27,37.77 -985.27,40.72 -918.78,107.22 DT3.1@-918.78,110.78
NetDT4_1: DT4.1 RT15.1 | length 74.5
  TOP w15: RT15.1@-682.01,183.8 -682.01,182.81 -678.5,179.31 DT4.1@-678.5,110.78
NetDT5_1: DT5.1 RT18.1 | length 98.6
  TOP w10: RT18.1@-985.27,-39.86 -985.27,-40.84 -918.78,-107.34 DT5.1@-918.78,-110.9
NetDT6_1: DT6.1 RT21.1 | length 72.5
  TOP w15: RT21.1@-682.01,-181.94 -682.01,-114.4 DT6.1@-678.5,-110.9
NetFT1_2: FT1.2 LT1.1
NetFT2_2: FT2.2 LT2.1
NetRB5_2: RB5.2 UB5.4 | length 174.9
  BOTTOM w10: RB5.2@131.49,103.05 185.77,103.05 191.63,97.19 191.63,57.17 191.49,57.03 191.49,17.01 201.38,7.12 207.49,7.12 207.61,7 UB5.4@219.42,7
NetRB8_2: RB8.2 UB4.6 | length 111.3
  BOTTOM w10: UB4.6@-13.46,47.79 -11.57,45.9 -11.57,29.17 -1.19,18.78 58.77,18.78 RB8.2@71,31.01
NetRT1_2: RT1.2 RT3.1 RT4.2 | length 695.1
  TOP w20: RT1.2@-543.06,1497.82 -539.2,1493.96 -480.02,1493.96 RT3.1@-474.04,1487.98 -473.55,1488.47 -473.55,1535.99 v1(-473.06,1536.48) ; RT4.2@-53.06,1414.99 -52.43,1414.37 -13.19,1414.37 v1(-12.57,1413.75)
  LAYER3 w20: v1(-473.06,1536.48) -456.84,1552.7 -139,1552.7 -13.34,1427.04 -13.34,1414.51 v1(-12.57,1413.75)
NetRT27_1: RT27.1 UB8.5 | length 201.4
  TOP w15: v1(776.94,-863.52) 776.94,-784.03 830.96,-730.01 RT27.1@832.93,-730.01
  BOTTOM w15: v1(776.94,-863.52) 776.94,-861.08 782.41,-855.61 782.41,-830.47 783.77,-829.11 UB8.5@790.09,-829.11
NetRT28_1: RT28.1 UB8.1 UB8.2 | length 107.2
  TOP w15: RT28.1@932.93,-730.01 v1@989.98,-730.03
  BOTTOM w15: UB8.2@986.94,-777.93 UB8.1@986.94,-752.34 988.64,-752.34 990,-750.98 v1(990,-730.05)
NetRT31_2: RT31.2 RT32.1 UB8.6 | length 219.8
  TOP w15: RT32.1@830.96,-792.02 832.93,-792.02 858.95,-818.05 905.92,-818.05 919.76,-804.21 919.76,-802.24 929.98,-792.02 RT31.2@931.94,-792.02
  BOTTOM w15: UB8.6@790.09,-803.52 790.14,-803.47 863.08,-803.47 877.66,-818.05 v1(880.1,-818.05)
NetRT32_2: RT32.2 RT35.2 UB8.7 | length 332.5
  TOP w15: v1(802.58,-883.52) 804.3,-885.24 804.3,-891.35 824.98,-912.02 RT35.2@826.94,-912.02 829.44,-909.52 829.44,-857.51 RT32.2@831.94,-855.01
  LAYER2 w15: v1(802.58,-883.52) 859.27,-803.32 cw(c880.1,-818.05) 859.96,-802.39 v1(883.56,-772.05)
  BOTTOM w15: UB8.7@790.09,-777.93 875.24,-777.93 881.12,-772.05 v1(883.56,-772.05)
NetRT36_1: RT36.1 UT8.3 | length 67
  TOP w15: RT36.1@786.94,-1069.11 844.84,-1069.11 849.54,-1064.4 UT8.3@849.54,-1061.94
NetRT37_2: RT37.2 RT38.2 UT8.4 | length 254.3
  TOP w15: UT8.4@849.54,-1165.09 854.25,-1160.39 854.25,-1135.23 863.03,-1126.44 983.01,-1126.44 RT38.2@1005,-1104.45 1005,-1054.96 RT37.2@998.28,-1048.25
NetRT40_2: RT40.2 RT41.2 RT42.1 | length 802.5
  TOP w15: v1(-513.06,-1373.52) -511.33,-1375.24 -491.8,-1375.24 -453.06,-1413.99 RT41.2@-453.06,-1426.03 ; RT42.1@-56.07,-1489.02 14.1,-1489.02 RT40.2@23.94,-1498.86 16.07,-1498.86 -20.03,-1534.96 -20.03,-1541.6 v1(-21.75,-1543.33)
  LAYER3 w15: v1(-513.06,-1373.52) -396.69,-1489.88 -75.2,-1489.88 v1(-21.75,-1543.33)
NetUB6_4: UB6.4 UB7.6 | length 341.6
  BOTTOM w12: UB7.6@-37.51,-626.56 -37.51,-562.56 -105.01,-495.06 -105.01,-430.06 -76.73,-401.79 UB6.4@0.42,-401.79
NetUT4_4: UT4.4 UT5.2 UT5.5 | length 379.6
  TOP w10: v1(-66.83,-468.33) UT5.5@-42.25,-468.33 ; UT5.5@-39.53,-466.23 -39.53,-429.59 -0.16,-390.22 UT5.2@-0.16,-348.98
  TOP w15: UT4.4@-261.7,-400.65 -261.56,-400.79 -171.91,-400.79 v1(-171.78,-400.93)
  LAYER5 w15: v1(-171.78,-400.93) -104.38,-468.33 v1@-68.26,-468.33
